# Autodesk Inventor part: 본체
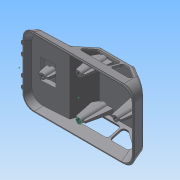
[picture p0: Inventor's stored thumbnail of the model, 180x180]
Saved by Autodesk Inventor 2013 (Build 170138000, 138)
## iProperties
Created: 2015-05
Part Number: 본체
Material: 일반
Document SubType Name: Modeling
Designer: ST3
Density: 1 g/cm^3
Author: ST3
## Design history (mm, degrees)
sketch "스케치1"
  geometry: L1 (-61, 0)-(61, 0); L2 (-61, 0)-(-58.588, 9); L3 (-58.588, 9)-(-19, 11.075); L4 (-19, 11.075)-(-6.549, 31); L5 (-6.549, 31)-(31, 31); L6 (31, 31)-(61, 11); L7 (57.412, 13.392)-(61, 0); L8 (61, 0)-(61, 11); 2 further points
  constraints: 16 end point, 2 horizontal, 2 midpoint, 1 coincident, 1 perpendicular, 1 point on line
  dimensions: "d0" = 122 distance of L1.start L1.end; "d2" = 105 deg angle of L1 L2; "d4" = 42 horizontal distance of L3.end L1.start; "d5" = 30 horizontal distance of L5.end L1.end; "d7" = 31 vertical distance of L1.end L5.end; "d8" = 125 deg angle of L4 L3; "d9" = 9 vertical distance of L2.end L1.start; "d10" = 3 deg angle of L1 L3; "d11" = 105 deg angle of L1 L7; "d99" = 20 vertical distance of L6.end L5.end
extrude "돌출1" new body sketch "스케치1" stored distance "d12" = 76; taper "d13" = 0 deg
sketch "스케치2"
  geometry: L1 (31, 38)-(11.075, 38) reference; L2 (31, -38)-(31, 38) reference; L3 (0, 38)-(31, 29.694); L4 (0, -38)-(31, -29.694); L5 (11.075, -38)-(31, -38) reference; L6 (0, -38)-(9, -38) reference; L7 (9, -38)-(11.075, -38) reference; L8 (11.075, 38)-(9, 38) reference; L9 (0, 38)-(31, 38); L10 (31, 38)-(31, 29.694); L11 (31, -29.694)-(31, -38); L12 (31, -38)-(0, -38); 1 further point
  constraints: 12 end point, 3 collinear, 2 point on line, 1 perpendicular
extrude "돌출2" cut sketch "스케치2" stored distance "d16" = 130; taper "d17" = 0 deg
sketch "스케치3"
  geometry: L1 (-58.588, 9)-(-61, 0) reference; L2 (-19, 11.075)-(-58.588, 9) reference; L3 (-50.479, 9.425)-(-50.741, 14.418); L4 (-50.741, 14.418)-(-30.741, 15.466); L5 (-30.741, 15.466)-(-30.479, 10.473); 1 further point
  constraints: 6 end point, 3 perpendicular, 2 point on line
  dimensions: "d18" = 20 horizontal distance of L3.end L4.end; "d20" = 11 distance from line of L3 L1.end; "d21" = 5 distance between parallel lines of L2 L4
extrude "돌출3" join sketch "스케치3" stored distance "d22" = 26; taper "d23" = 0 deg
feature "쉘1" dims "d24" = 2
sketch "스케치4"
  geometry: L1 (122, -76)-(122, 0) reference; L2 (0, 0)-(122, 0) reference; L3 (0, 0)-(0, -76) reference; L4 (122, -76)-(0, -76) reference; L5 (121, -1)-(121, -75); L6 (121, -75)-(1, -75); L7 (1, -75)-(1, -1); L8 (1, -1)-(121, -1); 1 further point
  constraints: 8 end point, 3 other
  dimensions: "d25" = 1 distance between parallel lines of L2 L8
extrude "돌출4" cut sketch "스케치4" distance "d26" = 1; taper "d27" = 0 deg
sketch "스케치6"
  geometry: L1 (121.732, -0.268)-(121.732, -75.732) reference; C1 r 3 at (100.732, -38); 1 further point
  constraints: 1 centre point, 1 horizontal alignment
  dimensions: "d33" = 6 diameter of C1; "d35" = 21 distance from line of L1 C1.centre
extrude "돌출5" join sketch "스케치6" stored distance "d36" = 10; taper "d37" = 2 deg
sketch "스케치8"
  geometry: L1 (34.732, 2)-(44.732, 2); L2 (58.929, 0)-(-58.929, 0) reference; L3 (34.732, 2)-(29.619, 31); L4 (44.732, 2)-(47.863, 19.758); L5 (42.732, 1)-(36.732, 1) reference; L6 (39.732, 1)-(39.732, 25.179); L7 (57.412, 13.392)-(31, 31) reference; L8 (31, 31)-(-6.549, 31) reference; 1 further point
  constraints: 8 end point, 3 point on line, 1 horizontal, 1 midpoint, 1 perpendicular
  dimensions: "d38" = 2 distance between parallel lines of L2 L1; "d39" = 20 deg angle of L4 L3; "d40" = 10 deg angle of L6 L3; "d41" = 5 distance from line of L6 L1.start; "d42" = 10 distance of L1.end L1.start
extrude "돌출6" join sketch "스케치8" stored distance "d43" = 2; taper "d44" = 0 deg
feature "면 기울기1" dims angle "d45" = 2.5 deg
feature "면 기울기2" dims angle "d46" = 2.5 deg
feature "면 기울기3" dims angle "d47" = 2.5 deg
feature "면 기울기4" dims angle "d48" = 2.5 deg
feature "면 기울기5" dims angle "d49" = 2.5 deg
feature "면 기울기6" dims angle "d50" = 2.5 deg
feature "면 기울기7" dims angle "d51" = 2.5 deg
feature "면 기울기8" dims angle "d52" = 2.5 deg
sketch "스케치9"
  geometry: L1 (-50.741, 14.418)-(-30.741, 15.466) reference; L2 (-50.741, 14.418)-(-30.741, 15.466); L3 (-30.945, 15.456)-(-26.502, 34.9); L4 (-26.502, 34.9)-(-51.656, 31.886); L5 (-51.656, 31.886)-(-50.741, 14.418); 1 further point
  constraints: 8 end point, 1 collinear, 1 perpendicular, 1 point on line
extrude "돌출7" cut sketch "스케치9" stored distance "d53" = 20; taper "d54" = 0 deg
sketch "스케치10"
  geometry: L1 (121.732, -0.268)-(121.732, -75.732) reference; C1 r 3 at (60.732, -60); 1 further point
  constraints: 1 centre point
  dimensions: "d55" = 61 distance from line of L1 C1.centre; "d56" = 22 vertical distance of C1.centre point (61, -38); "d57" = 6 diameter of C1
extrude "돌출8" join sketch "스케치10" stored distance "d58" = 20; taper "d59" = 2 deg
node "작업 평면1"
sketch "스케치11"
  geometry: L1 (3.268, 1)-(-2.732, 1) reference; L2 (4.246, 29)-(-3.71, 29) reference; L3 (3.268, 1)-(4.246, 29) reference; L4 (-30.394, 29)-(-55.675, 12.146) reference; L5 (-55.675, 12.146)-(-58.929, 0) reference; L6 (58.929, 0)-(-58.929, 0) reference; L7 (58.929, 0)-(57.033, 7.079) reference; L8 (57.033, 7.079)-(17.856, 9.132) reference; L9 (17.856, 9.132)-(5.441, 29) reference; L10 (5.441, 29)-(-30.394, 29) reference; L11 (-2.732, 1)-(-3.71, 29) reference; L12 (-4.732, 3)-(5.268, 3); L13 (5.268, 3)-(8.882, 23.494); L14 (-4.732, 3)-(-9.317, 29); L15 (0.268, 1)-(0.268, 29); 1 further point
  constraints: 8 end point, 2 midpoint, 2 point on line, 1 parallel, 1 perpendicular
  dimensions: "d61" = 20 deg angle of L13 L14; "d62" = 10 deg angle of L15 L14; "d63" = 2 distance between parallel lines of L12 L1; "d64" = 10 distance of L12.end L12.start; "d65" = 5 distance from line of L15 L12.start
extrude "돌출9" join sketch "스케치11" stored distance "d66" = 2; taper "d67" = 0 deg
feature "면 기울기9" dims angle "d68" = 2.5 deg
feature "면 기울기10" dims angle "d69" = 2.5 deg
feature "면 기울기11" dims angle "d70" = 2.5 deg
feature "면 기울기12" dims angle "d71" = 2.5 deg
sketch "스케치12"
  geometry: C1 r 3 at (0, 0) reference; 2 further points
  constraints: 1 coincident
sketch "스케치13"
  geometry: C1 r 3 at (0, 0) reference; 2 further points
  constraints: 1 coincident
hole "구멍1" sketch "스케치12" diameter "d72" = 3.242; stored, may be unused: countersink angle "d76" = 90 deg, drill point angle "d78" = 118 deg; dims "d73" = 9, "d74" = 4, "d75" = 2, "d77" = 11
sketch "스케치14"
  geometry: C1 r 3 at (0, 0) reference; 2 further points
  constraints: 1 coincident
hole "구멍2" sketch "스케치14" at (0, 0) diameter "d79" = 3.242; stored, may be unused: countersink angle "d83" = 90 deg, drill point angle "d85" = 118 deg; dims "d80" = 9, "d81" = 4, "d82" = 2, "d84" = 11
sketch "스케치16"
  geometry: L1 (67.281, -67.426)-(67.281, 8.038) reference; 2 further points
  constraints: 1 horizontal alignment, 1 other
  dimensions: "d90" = 50 distance from line of L1 point (17.281, -29.694)
feature "엠보싱1" sketch "스케치16" dims "d91" = 0.5, "d92" = 0
fillet "모깎기1" dims "d93" = 12
fillet "모깎기2" dims "d94" = 12
fillet "모깎기3" dims "d95" = 12
fillet "모깎기4" dims "d96" = 12
sketch "스케치18"
  geometry: L1 (37.549, 0)-(49.849, -8.489) reference; L2 (0, 0)-(37.549, 0) reference; L3 (-12.451, -20.628)-(0, 0) reference; L4 (57.725, -20)-(35.991, -5); L5 (35.991, -5)-(2.822, -5); L6 (2.822, -5)-(-6.231, -20); L7 (-42.592, -31.058)-(55.69, -31.058) reference; L8 (-6.231, -20)-(57.725, -20); L9 (27.769, -5)-(27.769, -20); L10 (29.725, -5)-(29.725, -20); 5 further points; 2 other entities
  constraints: 12 end point, 4 point on line, 2 parallel, 2 perpendicular, 2 other
  dimensions: "d100" = 5 distance between parallel lines of L2 L5; "d101" = 15 vertical distance of L6.end L5.end; "d102" = 15 vertical distance of L4.start L4.end; "d103" = 5 distance between parallel lines of L6 L3; "d104" = 5 distance between parallel lines of L1 L4; "d105" = 34 distance from line of L9 L6.end; "d106" = 28 distance from line of L4.start L10
extrude "돌출10" cut sketch "스케치18" stored distance "d107" = 2; taper "d108" = 0 deg
fillet "모깎기5" dims "d109" = 3
node "작업 평면3"
sketch "스케치19"
  geometry: 1 further point
node "작업 평면4"
sketch "스케치20"
  geometry: L1 (-26.141, 0)-(26.141, 0) reference; A1 r 2 centre (-21, 0) between (-19, 0) and (-23, 0); A2 r 2 centre (-10, 0) between (-8, 0) and (-12, 0); 1 further point
  constraints: 6 point on line, 4 point on circle, 2 centre point
  dimensions: "d112" = 4 diameter of A2; "d114" = 4 diameter of A1; "d115" = 11 distance of A2.centre A1.centre; "d116" = 10 horizontal distance of point (0, -4.177) A2.centre
extrude "돌출11" join sketch "스케치20" stored distance "d117" = 2; taper "d118" = 0 deg
fillet "모깎기6" dims "d119" = 3
fillet "모깎기7" dims "d120" = 3
fillet "모깎기8" dims "d121" = 3
fillet "모깎기9" dims "d122" = 3
fillet "모깎기10" dims "d123" = 3
fillet "모깎기11" dims "d124" = 3
chamfer "모따기1" distance "d125" = 1; stored, may be unused: second distance "d126" = 2, angle "d127" = 45 deg
node "솔리드1"
mirror "대칭1"
mirror "대칭2"
mirror "대칭3"
mirror "대칭4"
mirror "대칭5"
mirror "대칭6"
mirror "대칭7"
mirror "대칭8"
node "투영된 루프2"
node "투영된 루프3"
node "작업 평면2"
other parameters: "d60" = -22, "d110" = 90 deg, "d111" = 2
